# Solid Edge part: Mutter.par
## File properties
Sűrűség: 0,000 kg/m^3
Pontosság: 0,990
Author: bmolnar
Last saved by: ahadarics
Revision: 76
Username: bmolnar
Dokumentum tartalom típus: 0
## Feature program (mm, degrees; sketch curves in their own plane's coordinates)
base feature "unnamed BaseFeature 1"
thread "unnamed Thread 1"
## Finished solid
Body 1: solid body, 23 faces, 46 edges, 24 vertices.
  Faces by surface: cone 14, plane 8, cylinder 1
  Edges by curve: spline 24, circle 16, line 6
Bounding box of the edges (mm): 8.000 x 27.713 x 24.000, from (0, -13.8564, -12) to (8, 13.8564, 12).
Cylindrical faces by radius (mm): R7.188 x1
Conical faces (half-angle, radius in mm at the cone's reference point): 60 deg R7.5939 x2, 60 deg R12.9282 x12
Planar faces by outward normal: +x 1, +z 1, -x 1, -z 1, oblique 4
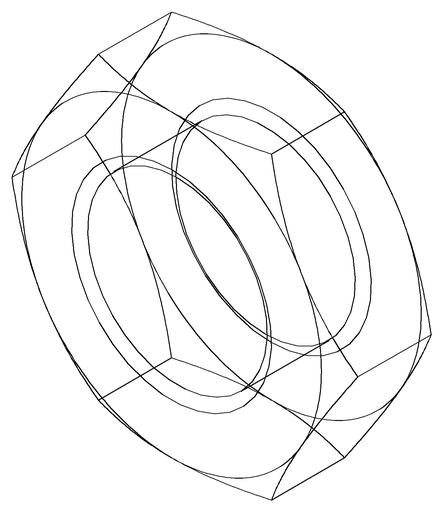
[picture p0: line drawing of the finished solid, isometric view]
